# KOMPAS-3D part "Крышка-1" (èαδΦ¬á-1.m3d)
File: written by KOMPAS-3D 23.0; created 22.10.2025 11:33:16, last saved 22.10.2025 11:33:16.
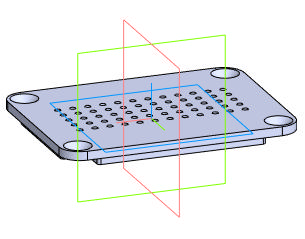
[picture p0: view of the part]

Document properties: Автор: ARM_513_VVK; Полное имя файла: F:\Демо\Демо вариант космос\Крышка-1.m3d

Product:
- Part/product: Крышка-1

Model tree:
1. Операция без истории:1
